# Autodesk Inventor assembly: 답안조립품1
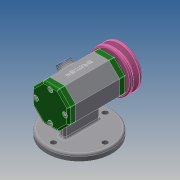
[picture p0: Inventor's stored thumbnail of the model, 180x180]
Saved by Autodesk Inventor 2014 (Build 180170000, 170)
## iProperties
Created: 2021-02
Part Number: 답안조립품1
Document SubType Name: Assembly
Designer: kb542-22
Author: kb542-22
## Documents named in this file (14)
- C:\Users\kb542-22\Desktop\답안조립품1.iam
- C:\Users\kb542-22\Desktop\본체.ipt
- C:\Users\kb542-22\Desktop\710204V1020\V벨트풀리.ipt
- C:\Users\kb542-22\Desktop\710204V1020\고무캡.ipt
- C:\Users\kb542-22\Desktop\710204V1020\너트 M8.ipt
- C:\Users\kb542-22\Desktop\710204V1020\뒤커버.ipt
- C:\Users\kb542-22\Desktop\710204V1020\베어링 15 x 32 x 9.ipt
- C:\Users\kb542-22\Desktop\710204V1020\볼트 M4 x 12.ipt
- C:\Users\kb542-22\Desktop\710204V1020\스프링와셔 8.ipt
- C:\Users\kb542-22\Desktop\710204V1020\앞커버.ipt
- C:\Users\kb542-22\Desktop\710204V1020\오일 실 15 25 7.ipt
- C:\Users\kb542-22\Desktop\710204V1020\와셔 8x17.ipt
- C:\Users\kb542-22\Desktop\710204V1020\축.ipt
- C:\Users\kb542-22\Desktop\710204V1020\키 3 x 3 x 12.ipt
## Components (2 placed, 2 different names)
1. V벨트풀리:1
2. 고무캡:1
